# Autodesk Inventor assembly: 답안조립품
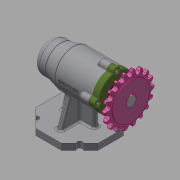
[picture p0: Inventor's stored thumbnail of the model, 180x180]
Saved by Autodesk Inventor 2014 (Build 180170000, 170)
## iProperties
Created: 2021-01
Part Number: 답안조립품
Document SubType Name: Assembly
Designer: kh
Author: kh
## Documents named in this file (12)
- C:\Users\kh\Downloads\710106V1018\답안조립품.iam
- C:\Users\kh\Downloads\710106V1018\본체.ipt
- C:\Users\kh\Downloads\710106V1018\멈춤나사 M3.ipt
- C:\Users\kh\Downloads\710106V1018\베어링 6004.ipt
- C:\Users\kh\Downloads\710106V1018\베어링 51202.ipt
- C:\Users\kh\Downloads\710106V1018\볼트 M4.ipt
- C:\Users\kh\Downloads\710106V1018\스프로킷.ipt
- C:\Users\kh\Downloads\710106V1018\어댑터슬리브.ipt
- C:\Users\kh\Downloads\710106V1018\오일 실.ipt
- C:\Users\kh\Downloads\710106V1018\축.ipt
- C:\Users\kh\Downloads\710106V1018\커버.ipt
- C:\Users\kh\Downloads\710106V1018\키 5 x 5 x 14.ipt
